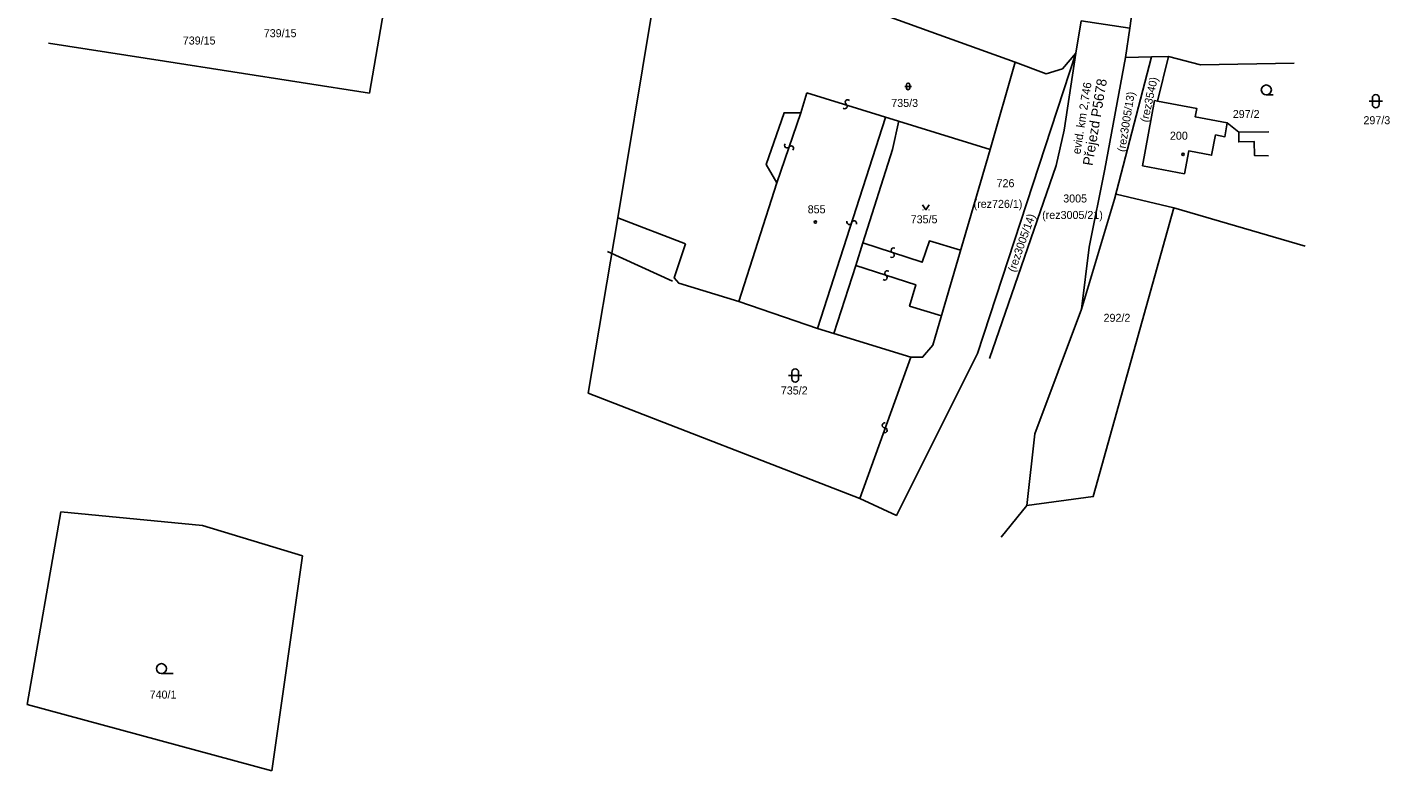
# Model space of a CAD drawing. Extents: x -728695 to -728301, y -1073159 to -1072856.
# Drawn here: x -728667.9 to -728463.6, y -1073159.3 to -1073047.8 of the extents above; entities that cross this region are included whole.
import ezdxf

# ---------------------------------------------------------------- set-up
doc = ezdxf.new("R2010")
doc.units = 0
for name, color, linetype in [('Dočasný_nad_1_rok', 7, 'Continuous'), ('Kóty', 7, 'Continuous'), ('Ostatní hranice analog mapa', 7, 'Continuous'), ('Trvalý_maska', 7, 'Continuous'), ('Trvalý_pro_SŽDC_dle_UMVZST', 7, 'Continuous'), ('Trvalý_XXX_ZPF', 7, 'Continuous'), ('Vedení_ koleje_ dráhy', 7, 'Continuous')]:
    doc.layers.add(name, color=color, linetype=linetype)

msp = doc.modelspace()

# ---------------------------------------------------------------- linework, layer by layer
at = {"layer": 'Dočasný_nad_1_rok'}
for centre in [(-728494.59, -1073066.86), (-728549.73, -1073077.02)]:
    msp.add_circle(centre, 0.175, dxfattribs=at)
at = {"layer": 'Kóty'}
for p, q in [((-728501.19, -1073037.94), (-728502.6, -1073047.92)), ((-728510.66, -1073051.71), (-728509.9, -1073046.86)), ((-728509.9, -1073046.86), (-728502.6, -1073047.92)), ((-728502.6, -1073047.92), (-728503.24, -1073052.34)), ((-728664.69, -1073050.2), (-728647.33, -1073052.89)), ((-728510.66, -1073051.71), (-728525.44, -1073096.73)), ((-728499.33, -1073052.26), (-728504.87, -1073073.55)), ((-728503.24, -1073052.34), (-728499.33, -1073052.26)), ((-728499.33, -1073052.26), (-728496.81, -1073052.21)), ((-728496.81, -1073052.21), (-728498.42, -1073058.87)), ((-728647.33, -1073052.89), (-728616.56, -1073057.69)), ((-728519.8, -1073053.05), (-728523.51, -1073066.11)), ((-728523.51, -1073066.11), (-728551, -1073057.61)), ((-728523.51, -1073066.11), (-728531.77, -1073094.25)), ((-728494.39, -1073069.77), (-728500.7, -1073068.59)), ((-728580.92, -1073081.44), (-728571.17, -1073085.87)), ((-728662.87, -1073120.46), (-728667.89, -1073149.35)), ((-728641.62, -1073122.5), (-728662.87, -1073120.46)), ((-728626.6, -1073127.02), (-728641.62, -1073122.5)), ((-728626.6, -1073127.02), (-728631.24, -1073159.26)), ((-728667.89, -1073149.35), (-728631.24, -1073159.26))]:
    msp.add_line(p, q, dxfattribs=at)
for points in [[(-728581.13, -1073030.83), (-728573.14, -1073034.08), (-728549.3, -1073042.35), (-728532.43, -1073048.47), (-728519.8, -1073053.05)], [(-728616.56, -1073057.69), (-728613.27, -1073038.52), (-728613.14, -1073034.24)], [(-728519.8, -1073053.05), (-728515.13, -1073054.76), (-728512.7, -1073054.03), (-728510.66, -1073051.71)], [(-728510.66, -1073051.71), (-728512.45, -1073063.25), (-728513.61, -1073068.54)], [(-728503.24, -1073052.34), (-728506.32, -1073069.08), (-728508.68, -1073080.79), (-728509.82, -1073090.06)], [(-728496.81, -1073052.21), (-728491.97, -1073053.44), (-728477.97, -1073053.19)], [(-728500.7, -1073068.59), (-728498.87, -1073058.79), (-728498.42, -1073058.87), (-728492.55, -1073059.96), (-728492.79, -1073061.21), (-728487.98, -1073062.11), (-728486.26, -1073063.51), (-728481.72, -1073063.46)]]:
    msp.add_lwpolyline(points, dxfattribs=at)
at = {"layer": 'Ostatní hranice analog mapa'}
for p, q in [((-728555.49, -1073071.14), (-728551.93, -1073060.61)), ((-728549.41, -1073092.94), (-728539.2, -1073061.32)), ((-728513.61, -1073068.54), (-728523.62, -1073097.44)), ((-728535.44, -1073097.26), (-728543.04, -1073118.43)), ((-728518.03, -1073119.52), (-728521.86, -1073124.25))]:
    msp.add_line(p, q, dxfattribs=at)
for points in [[(-728573.14, -1073034.08), (-728574.38, -1073046.48), (-728579.35, -1073076.38)], [(-728551, -1073057.61), (-728551.93, -1073060.61), (-728554.43, -1073060.61), (-728557.09, -1073068.4), (-728555.49, -1073071.14), (-728561.23, -1073088.92)], [(-728537.21, -1073061.82), (-728538.15, -1073066.11), (-728542.63, -1073080.12), (-728543.66, -1073083.54), (-728546.95, -1073093.69)], [(-728476.28, -1073080.62), (-728496, -1073074.89), (-728504.64, -1073072.8)], [(-728504.87, -1073073.55), (-728509.82, -1073090.06), (-728516.82, -1073108.74), (-728518.03, -1073119.52), (-728508.07, -1073118.15), (-728496, -1073074.89)], [(-728579.35, -1073076.38), (-728583.79, -1073102.65), (-728543.04, -1073118.43), (-728537.57, -1073120.98), (-728525.44, -1073096.73)], [(-728579.35, -1073076.38), (-728569.19, -1073080.26)], [(-728569.19, -1073080.26), (-728570.9, -1073085.35), (-728570.21, -1073086.16), (-728561.23, -1073088.92), (-728549.41, -1073092.94), (-728546.95, -1073093.69), (-728535.44, -1073097.26), (-728533.66, -1073097.26), (-728532.13, -1073095.45), (-728531.77, -1073094.25)], [(-728542.63, -1073080.12), (-728533.71, -1073083.04), (-728532.62, -1073079.83), (-728527.95, -1073081.23)], [(-728530.83, -1073091.05), (-728535.61, -1073089.59), (-728534.69, -1073086.41), (-728543.66, -1073083.54)]]:
    msp.add_lwpolyline(points, dxfattribs=at)
at = {"layer": 'Trvalý_maska'}
for points in [[(-728494.39, -1073069.77), (-728493.75, -1073066.34), (-728490.32, -1073066.98), (-728489.74, -1073063.94), (-728488.34, -1073064.21), (-728487.98, -1073062.11)], [(-728486.26, -1073063.51), (-728486.26, -1073064.99), (-728483.93, -1073064.95), (-728483.88, -1073067.05), (-728481.77, -1073067.07)]]:
    msp.add_lwpolyline(points, dxfattribs=at)
at = {"layer": 'Trvalý_XXX_ZPF'}
for p, q in [((-728536.34, -1073056.68), (-728535.34, -1073056.68)), ((-728536.09, -1073056.43), (-728536.09, -1073056.93)), ((-728535.59, -1073056.43), (-728535.59, -1073056.93)), ((-728482.12, -1073057.95), (-728481.12, -1073057.95)), ((-728466.72, -1073058.89), (-728464.72, -1073058.89)), ((-728466.22, -1073058.39), (-728466.22, -1073059.39)), ((-728465.22, -1073058.39), (-728465.22, -1073059.39)), ((-728533.63, -1073075.15), (-728533.58, -1073075.15)), ((-728532.73, -1073075.15), (-728532.68, -1073075.15)), ((-728553.24, -1073099.51), (-728553.24, -1073100.51)), ((-728552.24, -1073099.51), (-728552.24, -1073100.51)), ((-728553.74, -1073100.01), (-728551.74, -1073100.01)), ((-728647.77, -1073144.7), (-728646.02, -1073144.7))]:
    msp.add_line(p, q, dxfattribs=at)
msp.add_lwpolyline([(-728533.65, -1073074.4), (-728533.15, -1073075.15), (-728532.65, -1073074.4)], dxfattribs=at)
for centre in [(-728482.12, -1073057.2), (-728647.77, -1073143.95)]:
    msp.add_circle(centre, 0.75, dxfattribs=at)
for centre, radius, start, end in [((-728535.84, -1073056.43), 0.25, 0, 180), ((-728535.84, -1073056.93), 0.25, 180, 0), ((-728544.88, -1073059.04), 0.376, 47.7437, 234.0408), ((-728465.72, -1073058.39), 0.5, 0, 180), ((-728545.32, -1073059.65), 0.376, 227.7437, 54.0408), ((-728465.72, -1073059.39), 0.5, 180, 0), ((-728553.98, -1073065.53), 0.376, 137.7437, 324.0408), ((-728553.37, -1073065.97), 0.376, 317.7437, 144.0408), ((-728544.65, -1073076.99), 0.376, 158.8659, 345.163), ((-728543.93, -1073077.19), 0.376, 338.8659, 165.163), ((-728537.99, -1073081.25), 0.376, 60.9548, 247.2518), ((-728538.28, -1073081.94), 0.376, 240.9548, 67.2518), ((-728539.33, -1073085.33), 0.376, 234.1364, 60.4334), ((-728538.96, -1073084.67), 0.376, 54.1364, 240.4334), ((-728552.74, -1073099.51), 0.5, 0, 180), ((-728552.74, -1073100.51), 0.5, 180, 0), ((-728539.32, -1073107.46), 0.376, 83.0374, 269.3345), ((-728539.33, -1073108.21), 0.376, 263.0374, 89.3345)]:
    msp.add_arc(centre, radius, start, end, dxfattribs=at)
at = {"layer": 'Vedení_ koleje_ dráhy'}
msp.add_lwpolyline([(-728477.97, -1073053.19), (-728491.97, -1073053.44), (-728496.81, -1073052.21), (-728499.33, -1073052.26), (-728503.24, -1073052.34), (-728502.6, -1073047.92)], dxfattribs=at)

# ---------------------------------------------------------------- texts
at = {"layer": 'Trvalý_pro_SŽDC_dle_UMVZST'}
for s, p in [('739/15', (-728632.43, -1073049.29)), ('739/15', (-728644.57, -1073050.39)), ('735/3', (-728538.35, -1073059.75)), ('297/2', (-728487.15, -1073061.41)), ('297/3', (-728467.56, -1073062.34)), ('200', (-728496.57, -1073064.66)), ('726', (-728522.56, -1073071.78)), ('3005', (-728512.57, -1073074.07)), ('855', (-728550.88, -1073075.69)), ('(rez726/1)', (-728526.01, -1073074.88)), ('(rez3005/21)', (-728515.73, -1073076.54)), ('735/5', (-728535.44, -1073077.19)), ('292/2', (-728506.52, -1073091.96)), ('735/2', (-728554.91, -1073102.85)), ('740/1', (-728649.54, -1073148.44))]:
    msp.add_text(s, height=1.2, dxfattribs=at).set_placement(p)
for s, rotation, p in [('(rez3540)', 77.3647, (-728499.87, -1073062.12)), ('(rez3005/13)', 80.5728, (-728503.31, -1073066.55)), ('(rez3005/14)', 70.428, (-728519.79, -1073084.6))]:
    msp.add_text(s, height=1.2, rotation=rotation, dxfattribs=at).set_placement(p)
at = {"layer": 'Vedení_ koleje_ dráhy'}
for s, height, rotation, p in [('evid. km 2,746', 1.25, 80.9732, (-728510.01, -1073066.89)), ('Přejezd P5678', 1.5, 80.4567, (-728508.18, -1073068.63))]:
    msp.add_text(s, height=height, rotation=rotation, dxfattribs=at).set_placement(p)

doc.saveas('drawing.dxf')
